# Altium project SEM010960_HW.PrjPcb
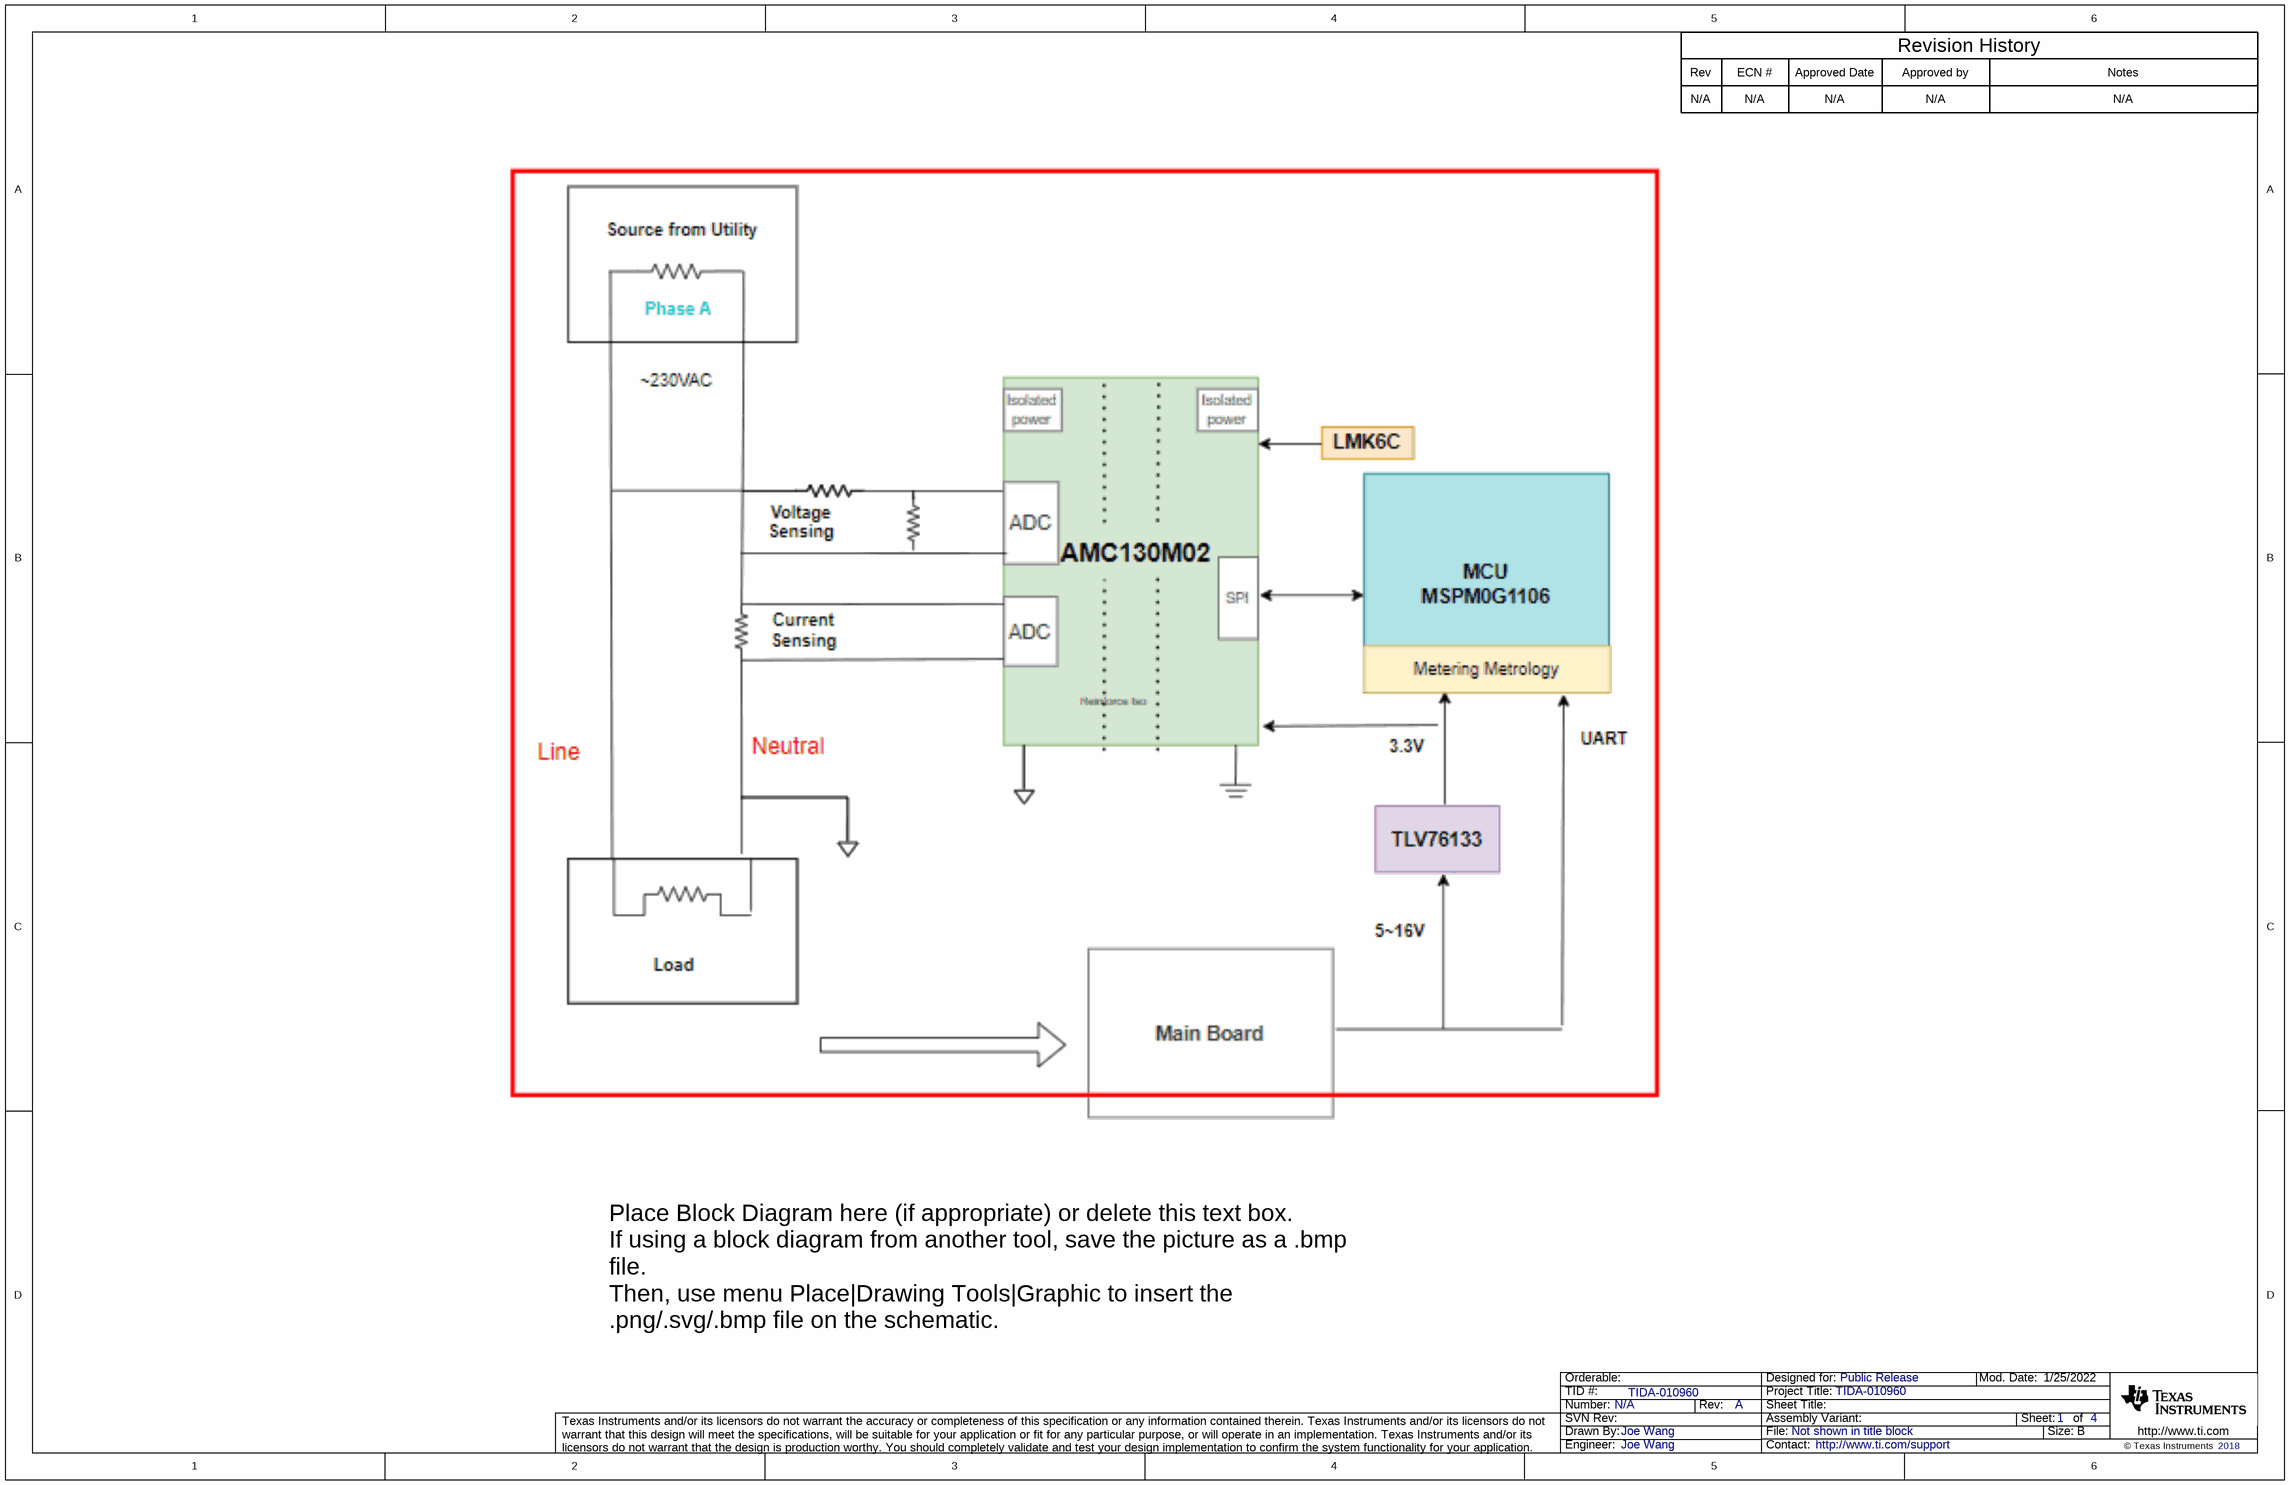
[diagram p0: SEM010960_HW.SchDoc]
CopyrightYear: 2018; PCB_Layout: Joe Wang; PCB_Rev: A; PRJ_Customer: Public Release; PRJ_Engineer: Joe Wang; PRJ_Number: N/A; PRJ_Title: TIDA-010960; SCH_Rev: A; TechSupport: http://www.ti.com/support; TID: TIDA-010960
4 sheets, 98 parts. Net scope: flat (ports and power ports of the same name join across sheets).
Board file: SEM010960_HW.PcbDoc
Sheets:
  SEM010960_HW.SchDoc
  SEM010960_HW_MSPM0.SchDoc
  SEM010960_HW_AMC.SchDoc
  SEM010960_HW_Hardware.SchDoc

## Sheet SEM010960_HW.SchDoc
size 431 x 279 mm; Date: Not shown in title block; ApprovedBy: Not shown in title block; CheckedBy: Not shown in title block; Author: Not shown in title block; CompanyName: Not shown in title block; DrawnBy: Joe Wang; Engineer: Not shown in title block; Organization: Not shown in title block; Address1: Not shown in title block; Address2: Not shown in title block; Address3: Not shown in title block; Address4: Not shown in title block; DocumentNumber: 1; Revision: Use project parameter SCH_Rev; SheetNumber: 1; SheetTotal: 4; PageSetup: Record=PageOptions¦CenterHorizontal=True¦CenterVertical=True¦PrintScale=1.00¦XCorrection=1.00¦YCorrection=1.00¦PrintKind=0¦BorderSize=5000000¦LeftOffset=0¦BottomOffset=0¦Orientation=2¦PaperLength=1000¦PaperWidth=1000¦Scale=100¦PaperSource=15¦PrintQuality=600¦MediaType=1¦DitherType=10¦PaperKind=Letter¦PrintScaleMode=1

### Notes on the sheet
- Rev
- N/A
- ECN #
- Approved Date
- Approved by
- Revision History
- Notes
- Place Block Diagram here (if appropriate) or delete this text box.
  If using a block diagram from another tool, save the picture as a .bmp file.
  Then, use menu Place|Drawing Tools|Graphic to insert the .png/.svg/.bmp file on the schematic.

## Sheet SEM010960_HW_MSPM0.SchDoc
size 431 x 279 mm; Date: Not shown in title block; ApprovedBy: Not shown in title block; CheckedBy: Not shown in title block; Author: Not shown in title block; CompanyName: Not shown in title block; DrawnBy: Joe Wang; Engineer: Not shown in title block; Organization: Not shown in title block; Address1: Not shown in title block; Address2: Not shown in title block; Address3: Not shown in title block; Address4: Not shown in title block; DocumentNumber: 2; Revision: Use project parameter SCH_Rev; SheetNumber: 2; SheetTotal: 4; PageSetup: Record=PageOptions¦CenterHorizontal=True¦CenterVertical=True¦PrintScale=1.00¦XCorrection=1.00¦YCorrection=1.00¦PrintKind=0¦BorderSize=5000000¦LeftOffset=0¦BottomOffset=0¦Orientation=2¦PaperLength=1000¦PaperWidth=1000¦Scale=100¦PaperSource=15¦PrintQuality=600¦MediaType=1¦DitherType=10¦PaperKind=Letter¦PrintScaleMode=1
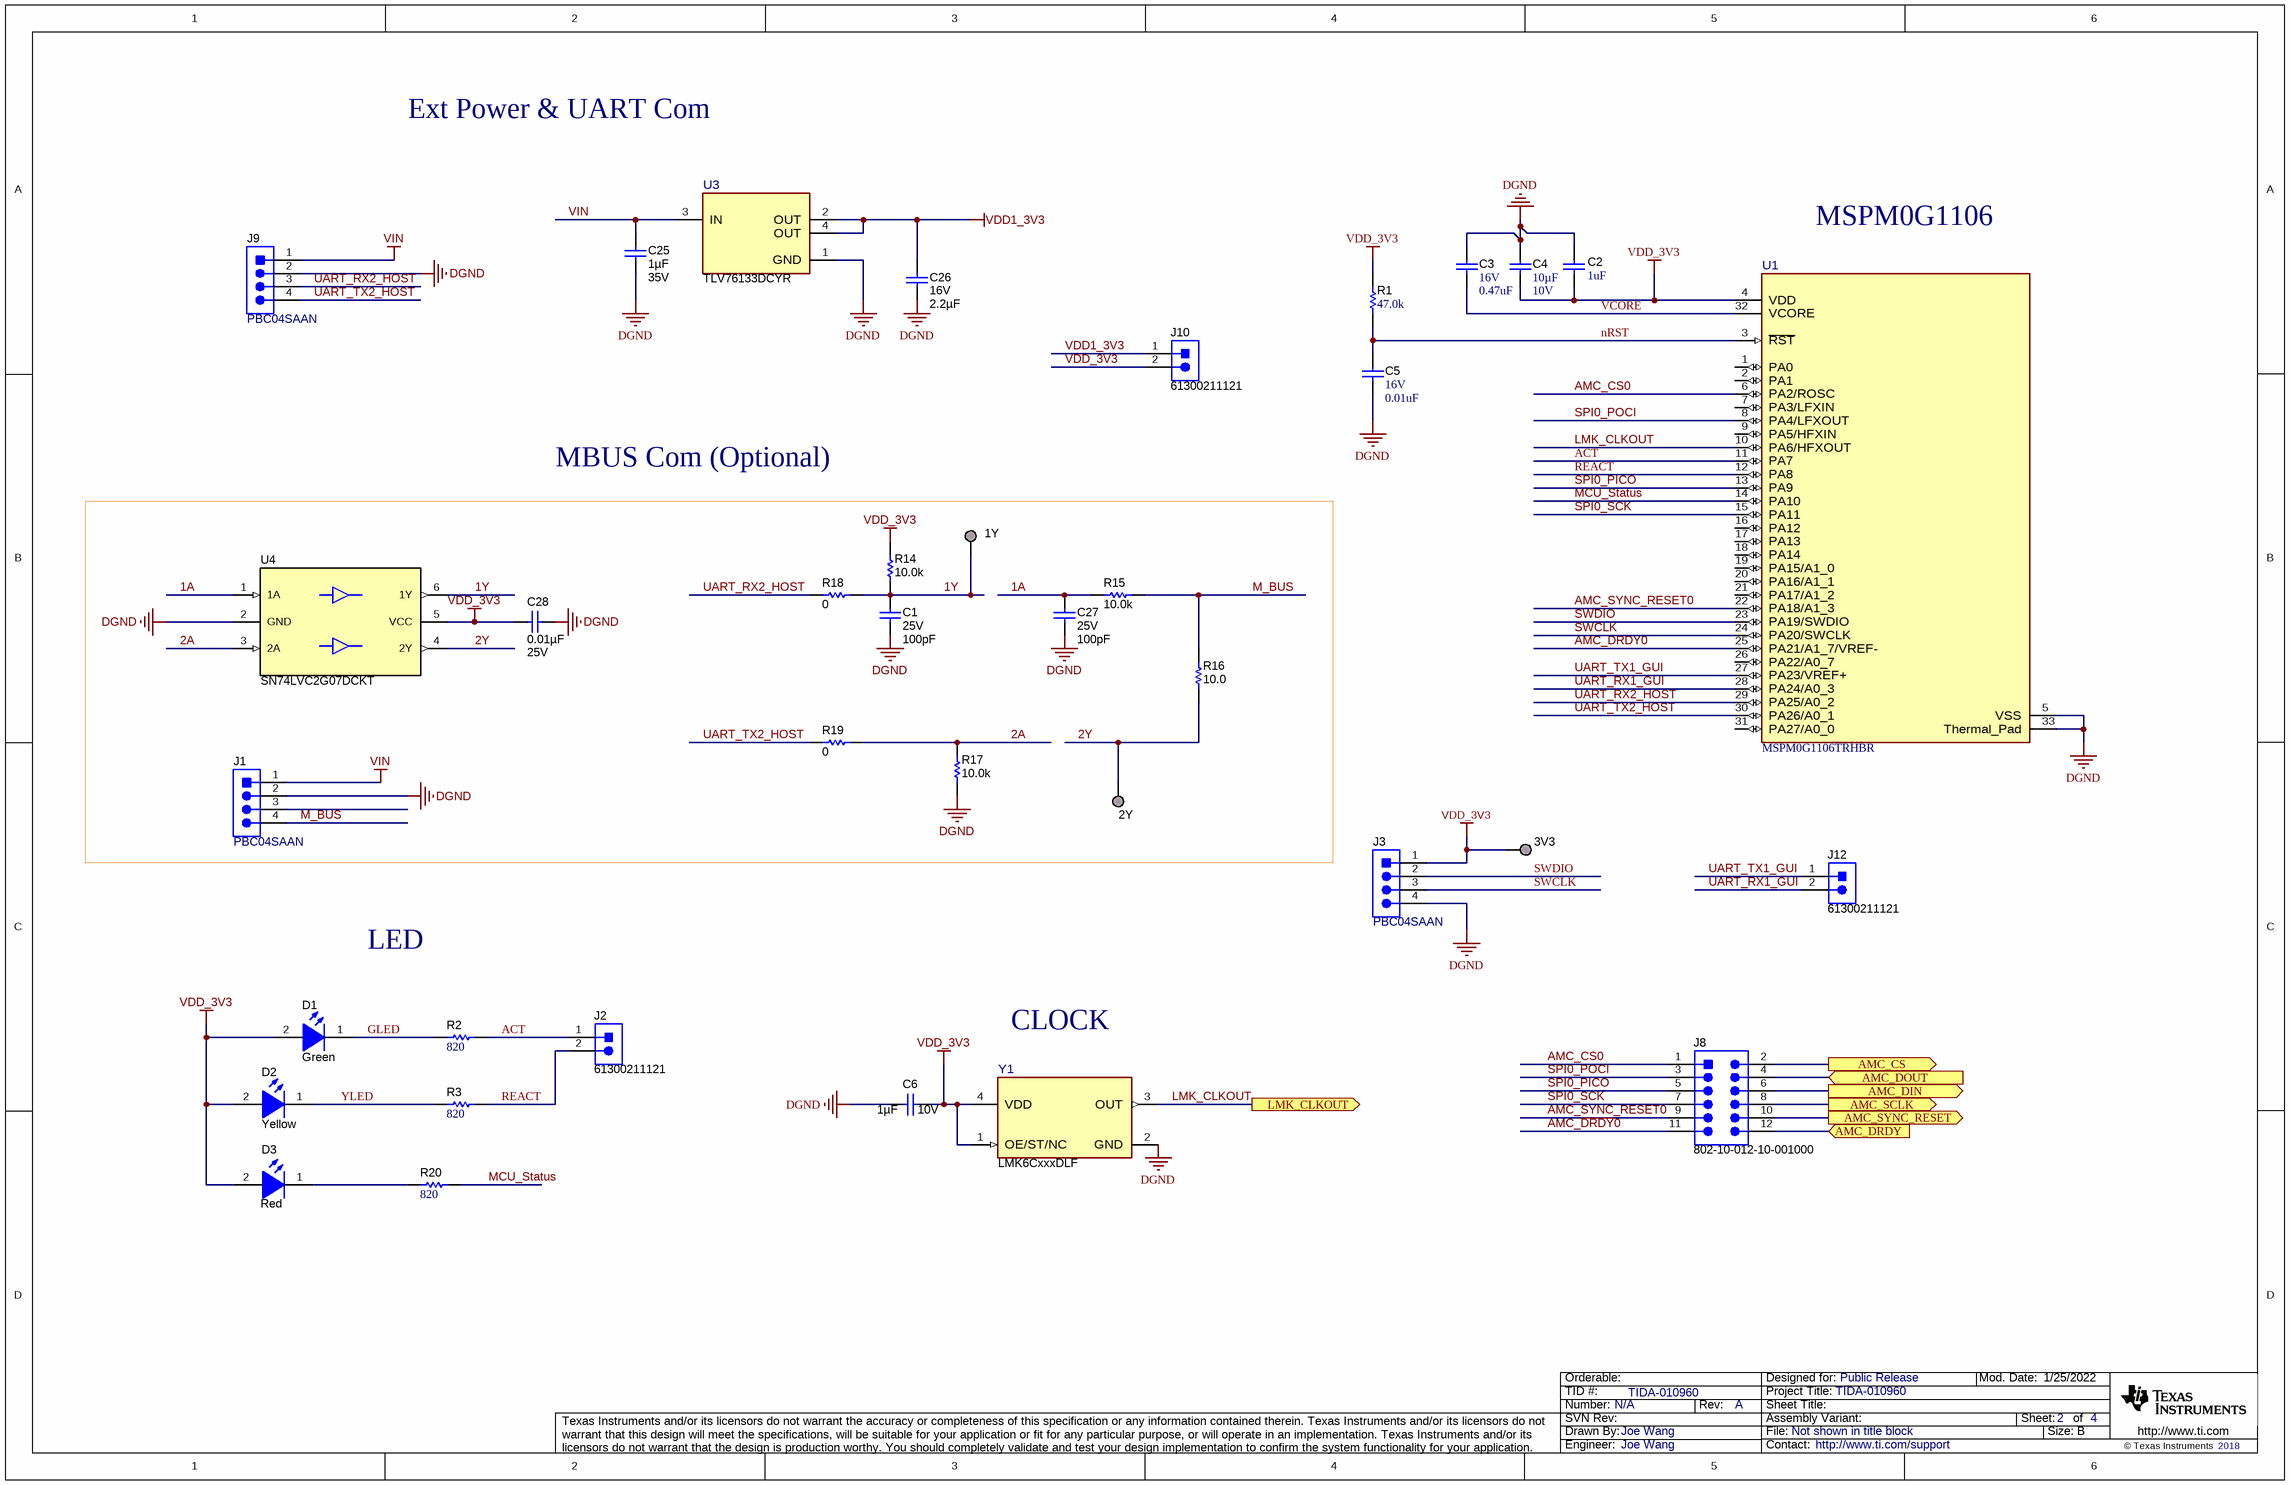
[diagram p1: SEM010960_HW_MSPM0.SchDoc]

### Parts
1Y  Testpoint_Gray  [Harwin_S2761-46R]  (value not drawn)
2Y  Testpoint_Gray  [Harwin_S2761-46R]  (value not drawn)
3V3  Testpoint_Gray  [Harwin_S2761-46R]  (value not drawn)
C1  VDC_V: 25V  ValueDisplayed: 100pF  [0402]  (hidden comment: C0402C101J3GACTU)
C2  ValueDisplayed: 1uF  [0402]  (hidden comment: GRM155R61A105KE15D)
C3  VDC_V: 16V  ValueDisplayed: 0.47uF  [0402]  (hidden comment: GRM155R61C474KE01)
C4  ValueDisplayed: 10µF  VDC_V: 10V  [0603]  (hidden comment: GRM188R61A106KAALD)
C5  VDC_V: 16V  ValueDisplayed: 0.01uF  [0402]  (hidden comment: C1005X7R1C103K050BA)
C6  Cap_F: 1µF  VDC_V: 10V  [0603]  (hidden comment: LMK107B7105KA-T)
C25  Cap_F: 1µF  VDC_V: 35V  [0603]  (hidden comment: CGA3E1X7R1V105K080AE)
C26  VDC_V: 16V  Cap_F: 2.2µF  [0603]  (hidden comment: GRM188Z71C225KE43)
C27  VDC_V: 25V  ValueDisplayed: 100pF  [0402]  (hidden comment: C0402C101J3GACTU)
C28  ValueDisplayed: 0.01µF  VDC_V: 25V  [0402]  (hidden comment: 04023C103JAT2A)
D1  value Green  [WL-SMCW_GREEN]  (hidden comment: 150060VS75000)
D2  value Yellow  [WL-SMCW_YELLOW]  (hidden comment: 150060YS75000)
D3  value Red  [WL-SMCW_RED]  (hidden comment: 150060RS75000)
J1  PBC04SAAN  [Sullins_xxC04SAAN]
J2  61300211121  [WURTH_61300211121]
J3  PBC04SAAN  [Sullins_xxC04SAAN]
J8  802-10-012-10-001000  [Mill-Max_802-10-012-10-001000]
J9  PBC04SAAN  [Sullins_xxC04SAAN]
J10  61300211121  [WURTH_61300211121]
J12  61300211121  [WURTH_61300211121]
R1  ValueDisplayed: 47.0k  [0402]  (hidden comment: RC0402FR-0747KL)
R2  value 820  [0402]  (hidden comment: RC0402FR-07820RL)
R3  value 820  [0402]  (hidden comment: RC0402FR-07820RL)
R14  ValueDisplayed: 10.0k  [0402]  (hidden comment: CRCW040210K0DHEDP)
R15  ValueDisplayed: 10.0k  [0402]  (hidden comment: CRCW040210K0DHEDP)
R16  ValueDisplayed: 10.0  [0402]  (hidden comment: CRCW040210R0FKED)
R17  ValueDisplayed: 10.0k  [0402]  (hidden comment: CRCW040210K0DHEDP)
R18  ValueDisplayed: 0  [0402]  (hidden comment: RC0402JR-070RL)
R19  ValueDisplayed: 0  [0402]  (hidden comment: RC0402JR-070RL)
R20  value 820  [0402]  (hidden comment: RC0402FR-07820RL)
U1  MSPM0G1106TRHBR  [RHB0032N-MFG]
U3  TLV76133DCYR  [DCY0004A-MFG]
U4  SN74LVC2G07DCKT  [DCK0006A_N]
Y1  LMK6CxxxDLF  [DLF0004A-MFG]

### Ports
AMC_CS (out), AMC_DIN (out), AMC_DOUT (in), AMC_DRDY (in), AMC_SCLK (out), AMC_SYNC_RESET (out), LMK_CLKOUT (out)

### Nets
DGND: C1.2 C2.2 C3.1 C4.1 C5.2 C6.2 C25.2 C26.2 C27.2 C28.2 J1.2 J3.4 J9.2 R17.1 U1.5(VSS) U1.33(Thermal_Pad) U3.1(GND) U4.2(GND) Y1.2(GND)
VDD1_3V3: C26.1 J10.1 U3.2(OUT) U3.4(OUT)
VDD_3V3: 3V3.1 C2.1 C4.2 C6.1 C28.1 D1.2(A) D2.2(A) D3.2(A) J3.1 J10.2 R1.2 R14.2 U1.4(VDD) U4.5(VCC) Y1.1(OE/ST/NC) Y1.4(VDD)
VIN: C25.1 J1.1 J9.1 U3.3(IN)
1A: C27.1 R15.1 U4.1(1A)
1Y: 1Y.1 C1.1 R14.1 R18.2 U4.6(1Y)
2A: R17.2 R19.2 U4.3(2A)
2Y: 2Y.1 R16.1 U4.4(2Y)
ACT: J2.1 R2.1 U1.11(PA7)
ADC_~{CS}: J8.2 ; port AMC_CS
ADC_DIN: J8.6 ; port AMC_DIN
ADC_DOUT: J8.4 ; port AMC_DOUT
ADC_SCLK: J8.8 ; port AMC_SCLK
AMC_CS0: J8.1 U1.6(PA2/ROSC)
AMC_~{DRDY}: J8.12 ; port AMC_DRDY
AMC_~{DRDY}0: J8.11 U1.25(PA21/A1_7/VREF-)
AMC_SYNC_RESET: J8.10 ; port AMC_SYNC_RESET
AMC_SYNC_RESET0: J8.9 U1.22(PA18/A1_3)
GLED: D1.1(K) R2.2
LMK_CLKOUT: U1.10(PA6/HFXOUT) Y1.3(OUT) ; port LMK_CLKOUT
M_BUS: J1.4 R15.2 R16.2
MCU_Status: R20.1 U1.14(PA10)
nRST: C5.1 R1.1 U1.3(~{RST})
REACT: J2.2 R3.1 U1.12(PA8)
SPI0_PICO: J8.5 U1.13(PA9)
SPI0_POCI: J8.3 U1.8(PA4/LFXOUT)
SPI0_SCK: J8.7 U1.15(PA11)
SWCLK: J3.3 U1.24(PA20/SWCLK)
SWDIO: J3.2 U1.23(PA19/SWDIO)
UART_RX1_GUI: J12.2 U1.28(PA24/A0_3)
UART_RX2_HOST: J9.3 R18.1 U1.29(PA25/A0_2)
UART_TX1_GUI: J12.1 U1.27(PA23/VREF+)
UART_TX2_HOST: J9.4 R19.1 U1.30(PA26/A0_1)
VCORE: C3.2 U1.32(VCORE)
YLED: D2.1(K) R3.2
NetD3_1: D3.1(K) R20.2

Not connected (* = marked no-connect by the designer): J1 3; U1 1(PA0) 2(PA1) 7(PA3/LFXIN) 9(PA5/HFXIN) 16(PA12) 17(PA13) 18(PA14) 19(PA15/A1_0) 20(PA16/A1_1) 21(PA17/A1_2) 26(PA22/A0_7) 31(PA27/A0_0)

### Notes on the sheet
- Ext Power & UART Com
- MSPM0G1106
- MBUS Com (Optional)
- LED
- CLOCK

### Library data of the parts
1Y 2Y 3V3 = CMP-0067619-1: Natural PC Test Point Brass, SMT; Manufacturer: Harwin; PartNumber: S2761-46R
C1 C27 = CMP-0006233-2: CAP, CERM, 100 pF, 25 V, +/- 5%, C0G/NP0, 0402; Manufacturer: Kemet; TaMin_C: -55°C; Polarized: N; SizeAreaWB_mm2: 3; Value1: Unknown; U/M: EA; Value: 100pF; TaMax_C: 125°C; SizeZ_mm: 0.6; SizeX_mm: 1; SizeY_mm: 0.5; AEC Category: Q200
C2 = CMP-0006563-2: CAP, CERM, 1 uF, 10 V, +/- 10%, X5R, 0402; Manufacturer: MuRata; TaMin_C: -55°C; Polarized: N; SizeAreaWB_mm2: 3; Value1: Unknown; U/M: EA; Value: 1uF; TaMax_C: 85°C; SizeZ_mm: 0.6; SizeX_mm: 1; SizeY_mm: 0.5; Value2: 10V; Cap_F: 1µF; AEC Category: Q200
C3 = CMP-0006600-2: CAP, CERM, 0.47 uF, 16 V, +/- 10%, X5R, 0402; Manufacturer: MuRata; TaMin_C: -55°C; Polarized: N; SizeAreaWB_mm2: 3; Value1: Unknown; U/M: EA; Value: 0.47uF; TaMax_C: 85°C; SizeZ_mm: 0.6; SizeX_mm: 1; SizeY_mm: 0.5; Cap_F: 470nF; AEC Category: Q200
C4 = CMP-0086193-1: CAP, CERM, 10 µF, 10 V,+/- 10%, X5R, 0603; Manufacturer: MuRata; SizeArea_mm2: 1.28; SizeY_mm: 0.8; TaMax_C: 85°C; TaMin_C: -55°C; Polarized: N; SizeAreaWB_mm2: 4.68; SizeZ_mm: 1; SizeX_mm: 1.6; AEC Category: Q200; U/M: EA; Value: 10uF
C5 = CMP-0006292-2: CAP, CERM, 0.01 uF, 16 V, +/- 10%, X7R, 0402; Manufacturer: TDK; TaMin_C: -55°C; Polarized: N; SizeAreaWB_mm2: 3; Value1: 0.0623 ohm; U/M: EA; Value: 0.01uF; TaMax_C: 125°C; SizeZ_mm: 0.6; SizeX_mm: 1; SizeY_mm: 0.5; Cap_F: 10nF; AEC Category: Q200; ESR_ohm: 62.3m
C6 = CMP-0080632-1: CAP, CERM, 1 µF, 10 V,+/- 10%, X7R, 0603; Manufacturer: Taiyo Yuden; SizeAreaWB_mm2: 4.68; SizeArea_mm2: 1.28; AEC Qualified: N; AEC Category: Q200; Value: 1uF; TaMax_C: 125°C; SizeZ_mm: 1; Green_REACh: Incomplete; TaMin_C: -55°C; SizeY_mm: 0.8; Green_Lifecycle: Active; U/M: EA; SizeX_mm: 1.6
C25 = CMP-0081259-1: CAP, CERM, 1 µF, 35 V,+/- 10%, X7R, AEC-Q200 Grade 1, 0603; Manufacturer: TDK; SizeAreaWB_mm2: 4.68; SizeArea_mm2: 1.28; AEC Qualified: Y; AEC Category: Q200; Value: 1uF; TaMax_C: 125°C; SizeZ_mm: 1; Polarized: N; TaMin_C: -55°C; SizeY_mm: 0.8; U/M: EA; SizeX_mm: 1.6
C26 = CMP-0007499-1: CAP, CERM, 2.2 uF, 16 V, +/- 10%, X7R, 0603; Manufacturer: MuRata; TaMin_C: -55°C; Polarized: N; SizeAreaWB_mm2: 4.68; Value1: Unknown; U/M: EA; Value: 2.2uF; TaMax_C: 125°C; SizeZ_mm: 1; SizeX_mm: 1.6; SizeY_mm: 0.8; SizeArea_mm2: 1.28; AEC Category: Q200
C28 = CMP-0085568-1: CAP, CERM, 0.01 µF, 25 V,+/- 5%, X7R, 0402; Manufacturer: AVX; AEC Category: Q200; SizeAreaWB_mm2: 3; SizeArea_mm2: 0.5; Polarized: N; TaMin_C: -55°C; Value: 0.01uF; U/M: EA; SizeX_mm: 1; Cap_F: 10nF; SizeZ_mm: 0.6; TaMax_C: 125°C
D1 = CMP-0002894-2: LED, Green, SMD; Manufacturer: Wurth Elektronik; Type: AlInGaP; Vf_V: 2V; Io_A: 20mA; Value1: W
D2 = CMP-0002892-3: LED, Yellow, SMD; Manufacturer: Wurth Elektronik; Type: AlInGaP; Vf_V: 2V; Io_A: 20mA; Value1: W
D3 = CMP-0002947-2: LED, Red, SMD; Manufacturer: Wurth Elektronik; Io_A: 30mA; Power_TotalModule: 72mW; Vr_V: 5V; Tjmax_C: 85°C; Value1: 0.072W; U/M: EA; Angle: 140; Vf_V: 2V; Type: AlInGaP
J1 J3 J9 = CMP-0054583-1: Header, 2.54 mm, 4x1, Gold, TH; Manufacturer: Sullins Connector Solutions; CNHeader: TRUE; Current_A: 3A; Green_Lifecycle: Not Set; Shrouded: N; Gender: Male; Green_REACh: Incomplete; Voltage_V: 1.8kV; Row_Count: 1; Pitch_mm: 2.54; CT: FALSE; Cert_UL: Y
J2 J10 J12 = CMP-0054794-2: Header, 2.54 mm, 2x1, Gold, TH; Manufacturer: Wurth Elektronik; Green_Lifecycle: Active; Shrouded: N; Gender: Male; Green_REACh: Passed; Row_Count: 1; Pitch_mm: 2.54; Cert_UL: Y
J8 = CMP-0055098-2: Header, 2.54 mm, 6x2, Gold, TH; Manufacturer: Mill-Max; Shrouded: N; Gender: Male; Row_Count: 2; RowSpacing_mm: 2.54
R1 = CMP-0026737-1: RES, 47.0 k, 1%, 0.0625 W, 0402; Manufacturer: Yageo America; Power_W: 62.5mW; TempCo: 100 ppm/C; Value_Code: 47k0; Value: 47.0k; Res_ohm: 47k; SizeX_mm: 1; SizeY_mm: 0.5; SizeZ_mm: 0.6; AEC Qualified: N; VDC_V: 50V; AEC Category: Q200; U/M: EA
R2 R3 R20 = CMP-0026743-1: RES, 820, 1%, 0.063 W, 0402; Manufacturer: Yageo America; Value_Code: 820R; Power_W: 63mW; Value2: 0.063W; VDC_V: 50V; TempCo: 100 ppm/C; U/M: EA; AEC Category: Q200; AEC Qualified: N; SizeArea_mm2: 0.5; SizeX_mm: 1; SizeZ_mm: 0.6
R14 R15 R17 = CMP-0026769-1: RES, 10.0 k, 0.5%, 0.063 W, 0402; Manufacturer: Vishay-Dale; Power_W: 63mW; TempCo: 50 ppm/C; Value_Code: 10k0; U/M: EA; Value: 10.0k; EIA_Code: E192; Res_ohm: 10k; SizeX_mm: 1; SizeY_mm: 0.5; SizeZ_mm: 0.6; Value2: 0.063W; VDC_V: 50V; AEC Category: Q200
R16 = CMP-0025963-3: RES, 10.0, 1%, 0.063 W, AEC-Q200 Grade 0, 0402; Manufacturer: Vishay-Dale; Power_W: 63mW; TempCo: 100 ppm/C; Value_Code: 10R0; Value: 10.0; EIA_Code: E96; Res_ohm: 10; SizeX_mm: 1; SizeY_mm: 0.5; SizeZ_mm: 0.6; Value2: 0.063W; AEC Qualified: Y; VDC_V: 50V; AEC Category: Q200; AEC Grade: 0
R18 R19 = CMP-0027004-1: RES, 0, 5%, 0.063 W, 0402; Manufacturer: Yageo America; Power_W: 63mW; TempCo: 200 ppm/C; Value_Code: 0000; U/M: EA; Value: 0; EIA_Code: E24; SizeX_mm: 1; SizeY_mm: 0.5; SizeZ_mm: 0.6; Value2: 0.063W; VDC_V: 50V; AEC Category: Q200
U1 = CMP-0095751-1: Mixed-Signal Microcontrollers VQFN32 ARM 32-bit Cortex-M0+ 80MHz 28 I/O's 64KB Flash 32KB SRAM; Manufacturer: Texas Instruments; AEC Qualified: No; Interface: I2C,SPI,UART,LIN,IrDA,SMBus; TJmax_C: +130°C; Number Of A/D Converters: 2; SizeZ_mm: 0.9mm; Max Supply Voltage: 3.6V; Core Architecture: ARM Cortex-M0+; Number Of Cores: 1; Standoff Height: 0mm; Memory Size: 64KBytes; Data Bus Width: 32bits; Number Of I/Os: 28; Number Of Timers/Counters: 7; Number Of Pwm Channels: 8; Number Of Uart Channels: 4; Ram Size: 32KBytes; Number Of Adc Channels: 10; TaMin_C: -40°C; Min Supply Voltage: 1.62V; TaMax_C: +105°C
U3 = CMP-0122558-1: 1-A 16-V high-PSRR linear voltage regulator 4-SOT-223 -40 to 125; Manufacturer: Texas Instruments; SizeZ_mm: 1.8mm; AEC Qualified: No; Accuracy Percentage: 1%; Dropout Voltage: 0.9V; Max Supply Voltage: 16V; Min Supply Voltage: 4.8V; Nominal Supply Current: 65uA; Number Of Outputs: 1; Output Type: Fixed; Output Voltage: 3.3V; Standoff Height: 0.02mm; TJmax_C: +125°C
U4 = CMP-0051787-3: Dual Buffer/Driver with Open-Drain Output, DCK0006A (SOT-SC70-6); Manufacturer: Texas Instruments; Alternate PartNumber: SN74LVC2G07DCKR; Output Type: CMOS; Bits(#): 2; Input Type: CMOS/TTL; Technology Family: LVC; Schmitt Trigger: No; VCC(Max)(V): 5.5; Sub-Family: Inverting Buffer/Driver; Rating: Catalog; Output Drive (IOL/IOH)(Max)(mA): 32/-32; ICC @ Nom Voltage(Max)(mA): 0.01; VCC(Min)(V): 1.65; F @ Nom Voltage(Max)(Mhz): 150; Logic: True; Voltage(Nom)(V): 1.8,2.5,3.3,5; tpd @ Nom Voltage(Max)(ns): 8.6,4.4,3.7,2.9; AEC Category: Q200; AEC Qualified: N; CompType: IC; Green_Lifecycle: Active; Green_REACh: Passed; SizeAreaWB_mm2: 9.3; SizeArea_mm2: 4.2; SizeX_mm: 2.1; SizeY_mm: 2.0; SizeZ_mm: 1.1
Y1 = CMP-0122603-1: Low Jitter, High-Performance BAW Oscillator; Manufacturer: Texas Instruments; SizeZ_mm: 1mm; AEC Qualified: No; Frequency Stability: 25ppm; Standoff Height: 0mm; TaMax_C: +105°C; TaMin_C: -40°C; TJmax_C: +125°C

## Sheet SEM010960_HW_AMC.SchDoc
size A3; Date: Not shown in title block; ApprovedBy: Not shown in title block; CheckedBy: Not shown in title block; Author: Not shown in title block; CompanyName: Not shown in title block; Engineer: Not shown in title block; Organization: Not shown in title block; Address1: Not shown in title block; Address2: Not shown in title block; Address3: Not shown in title block; Address4: Not shown in title block; DocumentNumber: 1; Revision: Use project parameter SCH_Rev; SheetNumber: 3; SheetTotal: 4; PageSetup: Record=PageOptions¦CenterHorizontal=True¦CenterVertical=True¦PrintScale=0.69¦XCorrection=1.00¦YCorrection=1.00¦PrintKind=0¦BorderSize=5000000¦LeftOffset=0¦BottomOffset=0¦Orientation=2¦PaperLength=1000¦PaperWidth=1000¦Scale=100¦PaperSource=15¦PrintQuality=600¦MediaType=1¦DitherType=10¦PaperKind=Letter¦PrintScaleMode=1
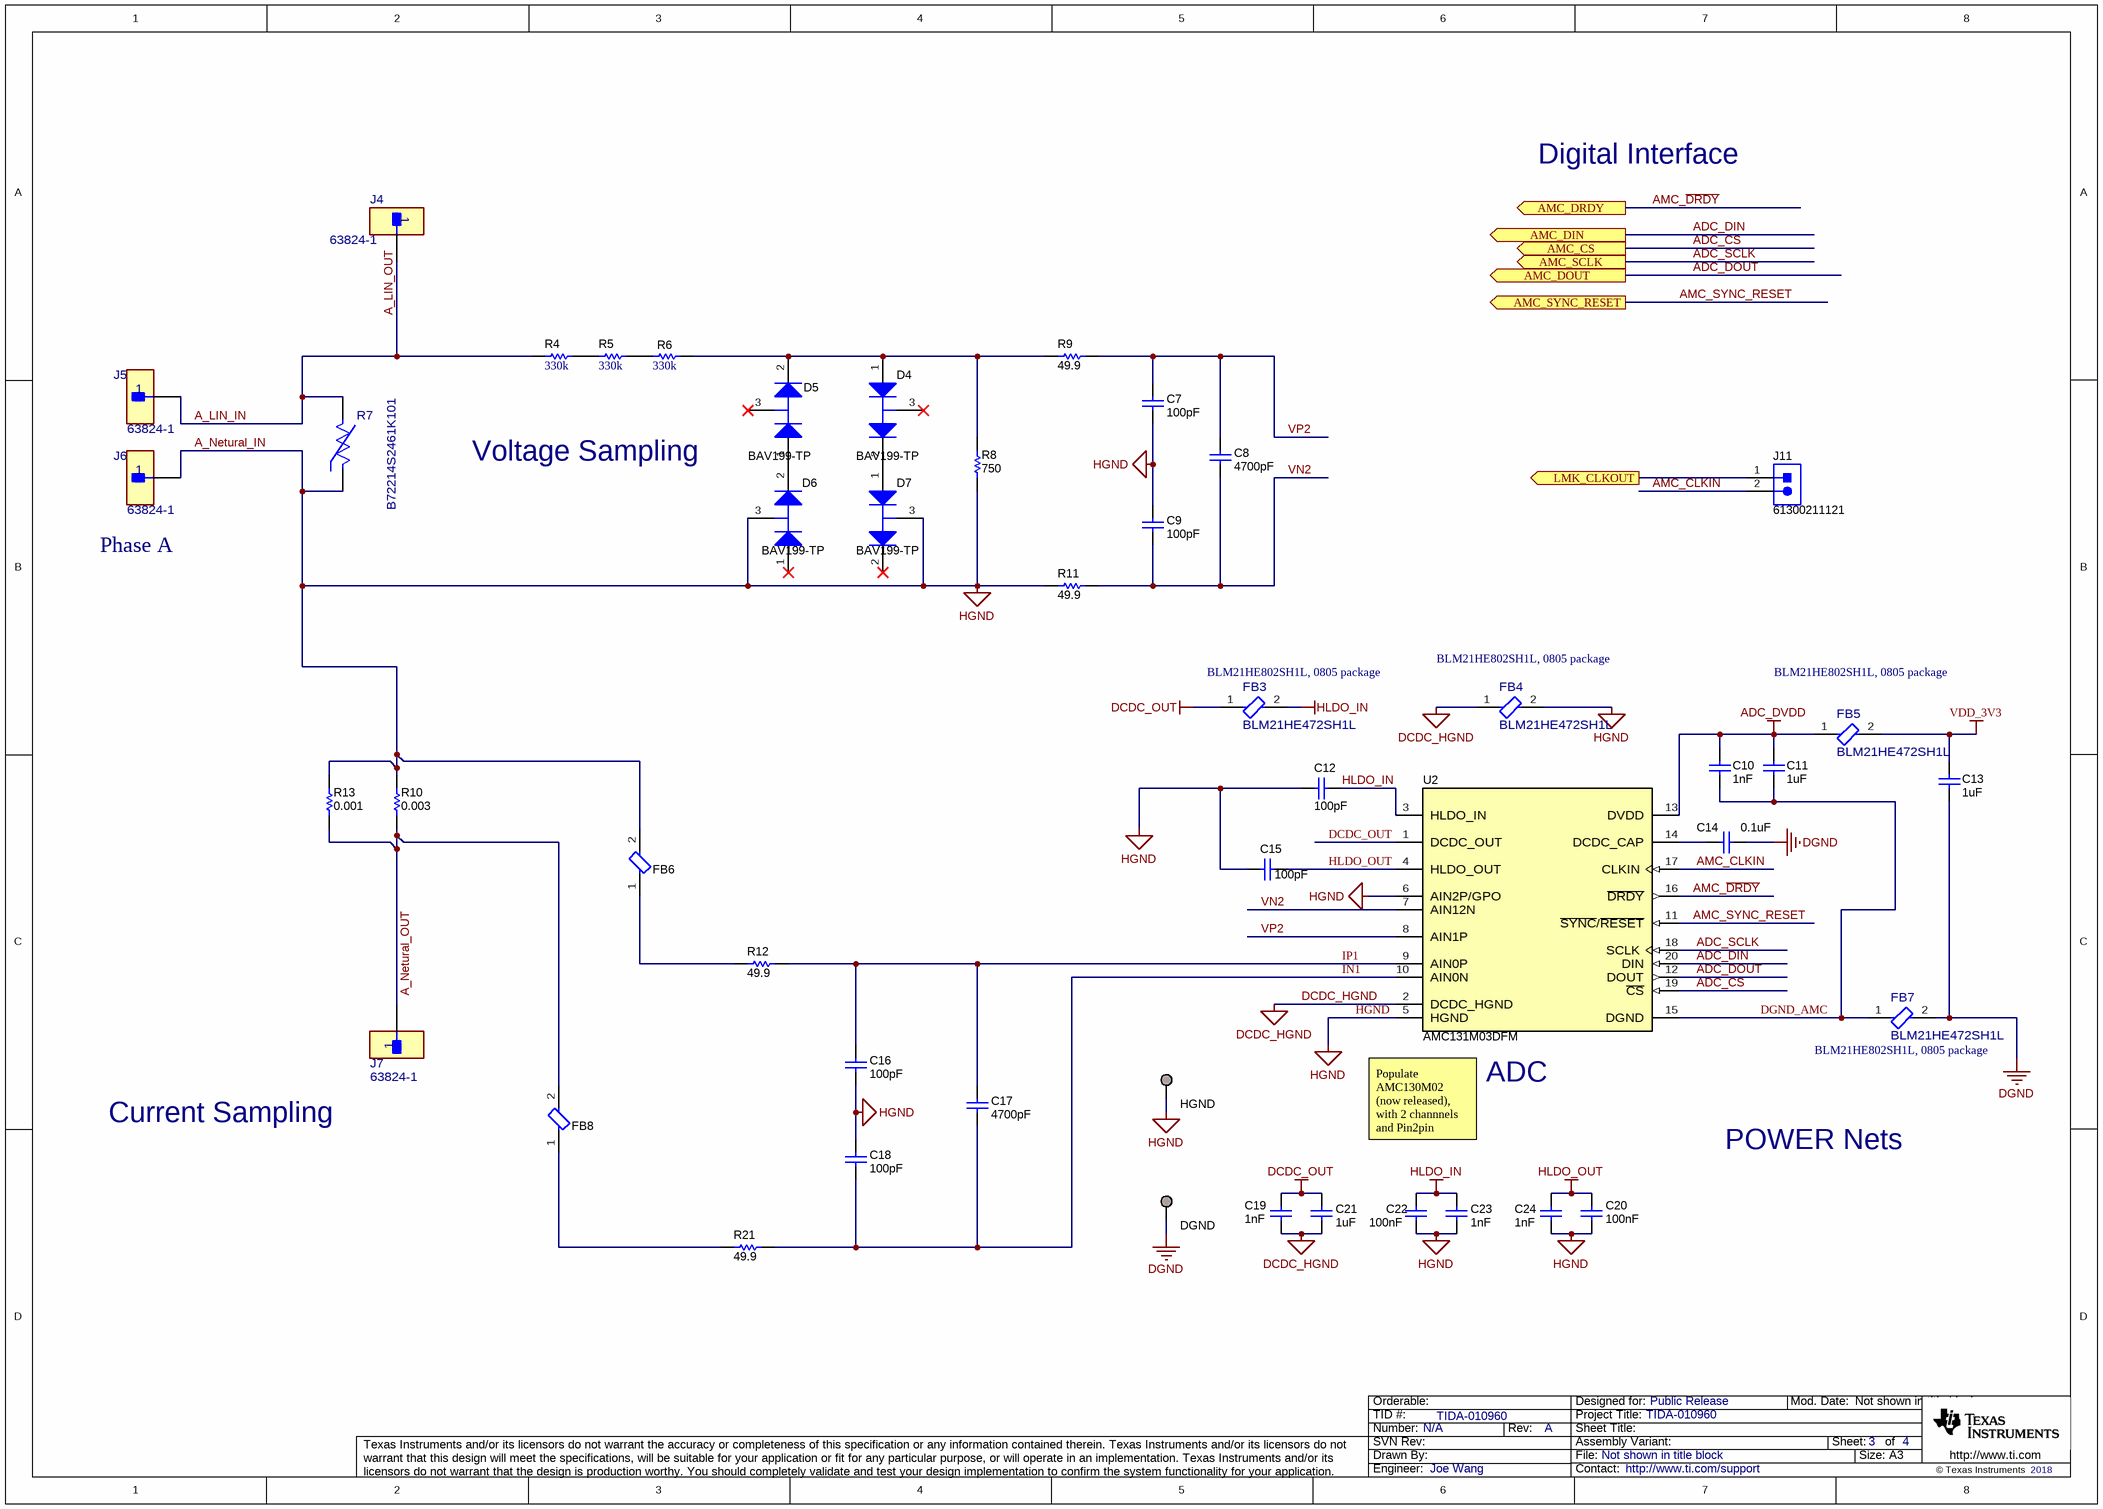
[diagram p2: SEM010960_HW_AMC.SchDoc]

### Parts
C7  ValueDisplayed: 100pF  [0603_HV]  (hidden comment: 885012006057)
C8  ValueDisplayed: 4700pF  [0603_HV]  (hidden comment: C0603C472J1GAC7867)
C9  ValueDisplayed: 100pF  [0603_HV]  (hidden comment: 885012006057)
C10  Cap_F: 1nF  [0603]  (hidden comment: C0603C102K5RACTU)
C11  ValueDisplayed: 1uF  [0603]  (hidden comment: C0603C105K3RACTU)
C12  ValueDisplayed: 100pF  [0603]  (hidden comment: 885012006057)
C13  ValueDisplayed: 1uF  [0603]  (hidden comment: C0603C105K3RACTU)
C14  value 0.1uF  [0603]  (hidden comment: C1608X7R1H104K080AA)
C15  ValueDisplayed: 100pF  [0603]  (hidden comment: 885012006057)
C16  ValueDisplayed: 100pF  [0603_HV]  (hidden comment: 885012006057)
C17  ValueDisplayed: 4700pF  [0603_HV]  (hidden comment: C0603C472J1GAC7867)
C18  ValueDisplayed: 100pF  [0603_HV]  (hidden comment: 885012006057)
C19  Cap_F: 1nF  [0603]  (hidden comment: C0603C102K5RACTU)
C20  Cap_F: 100nF  [0603]  (hidden comment: C1608X7R1H104K080AA)
C21  ValueDisplayed: 1uF  [0603]  (hidden comment: C0603C105K3RACTU)
C22  Cap_F: 100nF  [0603]  (hidden comment: C1608X7R1H104K080AA)
C23  Cap_F: 1nF  [0603]  (hidden comment: C0603C102K5RACTU)
C24  Cap_F: 1nF  [0603]  (hidden comment: C0603C102K5RACTU)
D4  BAV199-TP  [SOT-23L]
D5  BAV199-TP  [SOT-23L]
D6  BAV199-TP  [SOT-23L]
D7  BAV199-TP  [SOT-23L]
DGND  Testpoint_Gray  [Harwin_S2761-46R]  (value not drawn)
FB3  BLM21HE472SH1L  [FP-BLM21HE472SH1L_0805-MFG]
FB4  BLM21HE472SH1L  [FP-BLM21HE472SH1L_0805-MFG]
FB5  BLM21HE472SH1L  [FP-BLM21HE472SH1L_0805-MFG]
FB6  74269244182  [FP-74269244182_0402-MFG]  (value not drawn)
FB7  BLM21HE472SH1L  [FP-BLM21HE472SH1L_0805-MFG]
FB8  74269244182  [FP-74269244182_0402-MFG]  (value not drawn)
HGND  Testpoint_Gray  [Harwin_S2761-46R]  (value not drawn)
J4  63824-1  [FP-63824-1_CONN_7MM92_3MM11-MFG]
J5  63824-1  [FP-63824-1_CONN_7MM92_3MM11-MFG]
J6  63824-1  [FP-63824-1_CONN_7MM92_3MM11-MFG]
J7  63824-1  [FP-63824-1_CONN_7MM92_3MM11-MFG]
J11  61300211121  [WURTH_61300211121]
R4  ValueDisplayed: 330k  [TNPV1206]  (hidden comment: TNPV1206330KBEEN)
R5  ValueDisplayed: 330k  [TNPV1206]  (hidden comment: TNPV1206330KBEEN)
R6  ValueDisplayed: 330k  [TNPV1206]  (hidden comment: TNPV1206330KBEEN)
R7  B72214S2461K101  [FP-B72214S2461K101_RADIAL-MFG]
R8  ValueDisplayed: 750  [0603]  (hidden comment: RG1608P-751-B-T5)
R9  ValueDisplayed: 49.9  [0603]  (hidden comment: CRCW060349R9FKEA)
R10  ValueDisplayed: 0.003  [CRE2512-R1_R4]  (hidden comment: CRE2512-FZ-R003E-3)
R11  ValueDisplayed: 49.9  [0603]  (hidden comment: CRCW060349R9FKEA)
R12  ValueDisplayed: 49.9  [0603]  (hidden comment: CRCW060349R9FKEA)
R13  ValueDisplayed: 0.001  [1206]  (hidden comment: CRF1206-FZ-R001ELF)
R21  ValueDisplayed: 49.9  [0603]  (hidden comment: CRCW060349R9FKEA)
U2  AMC131M03DFM  [DFM0020A-MFG]

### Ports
AMC_CS (out), AMC_DIN (out), AMC_DOUT (out), AMC_DRDY (out), AMC_SCLK (out), AMC_SYNC_RESET (out), LMK_CLKOUT (out)

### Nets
A_Netural_IN: C7.2 C9.1 C12.1 C15.1 C16.2 C18.1 C20.2 C22.2 C23.2 C24.2 D6.3(C) D7.3(C) FB4.2 FB6.2 HGND.1 J6.1 R7.2 R8.1 R10.2 R11.1 R13.2 U2.5(HGND) U2.6(AIN2P/GPO)  [also labelled HGND]
ADC_DVDD: C10.1 C11.2 FB5.1 U2.13(DVDD)
DCDC_HGND: C19.2 C21.1 FB4.1 U2.2(DCDC_HGND)
DCDC_OUT: C19.1 C21.2 FB3.1 U2.1(DCDC_OUT)
DGND: C13.1 C14.2 DGND.1 FB7.2
HLDO_IN: C12.2 C22.1 C23.1 FB3.2 U2.3(HLDO_IN)
HLDO_OUT: C15.2 C20.1 C24.1 U2.4(HLDO_OUT)
VDD_3V3: C13.2 FB5.2
A_LIN_IN: J4.1 J5.1 R4.2 R7.1  [also labelled A_LIN_OUT]
A_Netural_OUT: FB8.2 J7.1 R10.1 R13.1
ADC_~{CS}: U2.19(~{CS}) ; port AMC_CS
ADC_DIN: U2.20(DIN) ; port AMC_DIN
ADC_DOUT: U2.12(DOUT) ; port AMC_DOUT
ADC_SCLK: U2.18(SCLK) ; port AMC_SCLK
AMC_CLKIN: J11.2 U2.17(CLKIN)
AMC_~{DRDY}: U2.16(~{DRDY}) ; port AMC_DRDY
AMC_SYNC_RESET: U2.11(~{SYNC}/~{RESET}) ; port AMC_SYNC_RESET
DGND_AMC: C10.2 C11.1 FB7.1 U2.15(DGND)
IN1: C17.2 C18.2 R21.2 U2.10(AIN0N)
IP1: C16.1 C17.1 R12.2 U2.9(AIN0P)
LMK_CLKOUT: J11.1 ; port LMK_CLKOUT
VN2: C8.2 C9.2 R11.2 U2.7(AIN12N)
VP2: C7.1 C8.1 R9.2 U2.8(AIN1P)
NetC14_1: C14.1 U2.14(DCDC_CAP)
NetD4_1: D4.1(A) D5.2(K) R6.2 R8.2 R9.1
NetD4_2: D4.2(K) D7.1(A)
NetD5_1: D5.1(A) D6.2(K)
NetFB6_1: FB6.1 R12.1
NetFB8_1: FB8.1 R21.1
NetR4_1: R4.1 R5.2
NetR5_1: R5.1 R6.1

Not connected (* = marked no-connect by the designer): D4 3(C)*; D5 3(C)*; D6 1(A)*; D7 2(K)*

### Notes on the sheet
- Digital Interface
- Voltage Sampling
- Phase A
- (near FB3) BLM21HE802SH1L, 0805 package
- (near FB4) BLM21HE802SH1L, 0805 package
- BLM21HE802SH1L, 0805 package
- (near FB7) BLM21HE802SH1L, 0805 package
- Current Sampling
- (near U2) ADC
- (near U2) Populate AMC130M02 (now released), with 2 channnels and Pin2pin package.
- POWER Nets

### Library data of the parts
C7 C9 C16 C18 = CMP-0006822-4: CAP, CERM, 100 pF, 50 V, +/- 5%, C0G/NP0, 0603; Manufacturer: Wurth Elektronik; TaMin_C: -55°C; Polarized: N; SizeAreaWB_mm2: 4.68; Value1: Unknown; U/M: EA; Value: 100pF; TaMax_C: 125°C; SizeZ_mm: 1; SizeX_mm: 1.6; SizeY_mm: 0.8; Cap_Case: 0603; Value2: 50V; SizeArea_mm2: 1.28; AEC Category: Q200
C8 C17 = CMP-0006941-4: CAP, CERM, 4700 pF, 100 V, +/- 5%, C0G/NP0, 0603; Manufacturer: Kemet; TaMin_C: -55°C; Polarized: N; SizeAreaWB_mm2: 4.68; Value1: Unknown; U/M: EA; Value: 4700pF; TaMax_C: 125°C; SizeZ_mm: 1; SizeX_mm: 1.6; SizeY_mm: 0.8; Cap_Case: 0603; Value2: 100V; SizeArea_mm2: 1.28; Cap_F: 4.7nF; AEC Category: Q200
C10 C19 C23 C24 = CMP-0006847-4: CAP, CERM, 1000 pF, 50 V, +/- 10%, X7R, 0603; Manufacturer: Kemet; TaMin_C: -55°C; Polarized: N; SizeAreaWB_mm2: 4.68; Value1: Unknown; U/M: EA; Value: 1000pF; TaMax_C: 125°C; SizeZ_mm: 1; SizeX_mm: 1.6; SizeY_mm: 0.8; Value2: 50V; SizeArea_mm2: 1.28; AEC Category: Q200
C11 C13 C21 = CMP-0006867-4: CAP, CERM, 1 uF, 25 V, +/- 10%, X7R, 0603; Manufacturer: Kemet; TaMin_C: -55°C; Polarized: N; SizeAreaWB_mm2: 4.68; Value1: Unknown; U/M: EA; Value: 1uF; TaMax_C: 125°C; SizeZ_mm: 1; SizeX_mm: 1.6; SizeY_mm: 0.8; Value2: 25V; SizeArea_mm2: 1.28; CompType: Capacitor; Cap_F: 1µF; AEC Category: Q200
C12 C15 = CMP-0006822-4: CAP, CERM, 100 pF, 50 V, +/- 5%, C0G/NP0, 0603; Manufacturer: Wurth Elektronik; TaMin_C: -55°C; Polarized: N; SizeAreaWB_mm2: 4.68; Value1: Unknown; U/M: EA; Value: 100pF; TaMax_C: 125°C; SizeZ_mm: 1; SizeX_mm: 1.6; SizeY_mm: 0.8; Value2: 50V; SizeArea_mm2: 1.28; AEC Category: Q200
C14 = CMP-0007044-5: CAP, CERM, 0.1 uF, 50 V, +/- 10%, X7R, 0603; Manufacturer: TDK; TaMin_C: -55°C; ESR_ohm: 29.6m; Polarized: N; SizeAreaWB_mm2: 4.68; Value1: 0.0296 ohm; U/M: EA; TaMax_C: 125°C; SizeZ_mm: 1; SizeX_mm: 1.6; SizeY_mm: 0.8; Value2: 50V; SizeArea_mm2: 1.28; IRMS_A: 971.99mA; AEC Category: Q200
C20 C22 = CMP-0007044-5: CAP, CERM, 0.1 uF, 50 V, +/- 10%, X7R, 0603; Manufacturer: TDK; TaMin_C: -55°C; ESR_ohm: 29.6m; Polarized: N; SizeAreaWB_mm2: 4.68; Value1: 0.0296 ohm; U/M: EA; Value: 0.1uF; TaMax_C: 125°C; SizeZ_mm: 1; SizeX_mm: 1.6; SizeY_mm: 0.8; Value2: 50V; SizeArea_mm2: 1.28; IRMS_A: 971.99mA; AEC Category: Q200
D4-D7 = CMP-0076968-2: Diode, Switching, 70 V, 0.215 A, SOT-23; Manufacturer: Micro Commercial Components; SizeZ_mm: 1.1; Vr_V: 70V; Value1: 0.215A; SizeArea_mm2: 7.5; TJmax_C: 150°C; SizeY_mm: 3.0; AEC Category: Q101; SizeAreaWB_mm2: 14.0; Io_A: 215mA; Value: 70V; SizeX_mm: 2.5; Green_Lifecycle: Not Set; Green_REACh: Incomplete
DGND HGND = CMP-0067619-1: as 1Y on sheet SEM010960_HW_MSPM0
FB3-FB5 FB7 = CMP-0037616-1: 4.7 kOhms @ 100 MHz 1 Signal Line Ferrite Bead 0805 (2012 Metric) 850mA 400mOhm; Manufacturer: Murata; DCR_ohm: 0.4; SizeZ_mm: 1.45mm; AEC Grade: Grade 1; AEC Qualified: Yes; Impedance At Frequency: 4700Ω @ 100MHz
FB6 FB8 = CMP-0091663-1: 1.8 kOhms @ 100MHz 1 Power, Signal Line Ferrite Bead 0402 (1005 Metric) 210mA 2.1Ohm; Manufacturer: Wurth Electronics; SizeZ_mm: 0.55mm; AEC Qualified: No; DCR_ohm: 2.1; Tolerance_%: 25%; Test Frequency: 1GHz; Impedance At Frequency: 1800Ω @ 100MHz
J4-J7 = CMP-0089624-1: Manufacturer: TE Connectivity; SizeZ_mm: 10.71mm; Conn Gender: Male; Conn Orientation: Straight; AEC Qualified: No; Import Ts: 1521847382; ContactFinish: Tin,Nickel; Current_A: 20A; Ciiva Ids: 766930
J11 = CMP-0054794-2: as J2 on sheet SEM010960_HW_MSPM0
R4-R6 = CMP-0018811-2: RES, 330 k, 0.1%, 1 W, 1206; Manufacturer: Vishay Draloric; Power_W: 1W; TempCo: 25 ppm/C; U/M: EA; Value: 330k; SizeX_mm: 3.2; SizeY_mm: 1.6; SizeZ_mm: 0.65; SizeArea_mm2: 5.12; AEC Qualified: N; VDC_V: 700V; AEC Category: Q200
R7 = CMP-0049856-1: Var MOV 460VAC/615VDC 5000A 750V Thru-Hole Radial Bulk; Manufacturer: TDK; SizeZ_mm: 19mm; AEC Qualified: No; Cap_F: 260pF; Clamping Voltage: 1240V; Vc: 50A; VDC_V: 615V; Voltage Tolerance: 10%
R8 = CMP-0023597-2: RES, 750, 0.1%, 0.1 W, 0603; Manufacturer: Susumu Co Ltd; Power_W: 100mW; TempCo: 25 ppm/C; Value_Code: 750R; U/M: EA; Value: 750; EIA_Code: E192; SizeX_mm: 1.6; SizeY_mm: 0.8; SizeZ_mm: 1; Value2: 0.1W; SizeArea_mm2: 1.28; VDC_V: 75V; AEC Category: Q200
R9 R11 R12 R21 = CMP-0022448-2: RES, 49.9, 1%, 0.1 W, 0603; Manufacturer: Vishay-Dale; Power_W: 100mW; TempCo: 100 ppm/C; Value_Code: 49R9; U/M: EA; Value: 49.9; EIA_Code: E96; SizeX_mm: 1.6; SizeY_mm: 0.8; SizeZ_mm: 1; Value2: 0.1W; SizeArea_mm2: 1.28; VDC_V: 75V; AEC Category: Q200
R10 = CMP-0015750-2: RES, 0.003, 1%, 3 W, AEC-Q200 Grade 0, 2512; Manufacturer: Bourns; Power_W: 3W; TempCo: 50 ppm/C; Value_Code: 3L000; U/M: EA; Value: 0.003; EIA_Code: E96; Res_ohm: 3m; SizeX_mm: 6.45; SizeY_mm: 3.35; SizeZ_mm: 0.9; SizeArea_mm2: 21.6075; AEC Qualified: Y; AEC Grade: 0; AEC Category: Q200
R13 = CMP-0078821-1: RES, 0.001, 1%, 1 W, AEC-Q200 Grade 0, 1206; Manufacturer: Bourns; Value_Code: 1L000; SizeArea_mm2: 5.12; AEC Qualified: Y; AEC Category: Q200; Res_ohm: 1m; Value: 0.001; SizeZ_mm: 1.35; EIA_Code: E96; TempCo: 50 ppm/C; AEC Grade: 0; SizeY_mm: 1.6; Power_W: 1W; SizeX_mm: 3.2
U2 = CMP-0093943-1: 3-Channel, Simultaneously-Sampling, 24-Bit, Reinforced Isolated DeltaSigma ADC With Integrated DC/DC Converter; Manufacturer: Texas Instruments; Interface: SPI; TaMax_C: +125°C; Standoff Height: 0.1mm; Resolution: 24bits; Max Supply Voltage: 5.5V; Data Polarity: Differential; Min Supply Voltage: 3V; TJmax_C: +150°C; Number Of Channels: 3; Sampling Rate: 32ksps; TaMin_C: -40°C; SizeZ_mm: 3.55mm; AEC Qualified: No

## Sheet SEM010960_HW_Hardware.SchDoc
size 431 x 279 mm; Date: Not shown in title block; ApprovedBy: Not shown in title block; CheckedBy: Not shown in title block; Author: Not shown in title block; CompanyName: Not shown in title block; Engineer: Not shown in title block; Organization: Not shown in title block; Address1: Not shown in title block; Address2: Not shown in title block; Address3: Not shown in title block; Address4: Not shown in title block; DocumentNumber: 3; Revision: Use project parameter SCH_Rev; SheetNumber: 4; SheetTotal: 4; PageSetup: Record=PageOptions¦CenterHorizontal=True¦CenterVertical=True¦PrintScale=1.00¦XCorrection=1.00¦YCorrection=1.00¦PrintKind=0¦BorderSize=5000000¦LeftOffset=0¦BottomOffset=0¦Orientation=2¦PaperLength=1000¦PaperWidth=1000¦Scale=100¦PaperSource=15¦PrintQuality=600¦MediaType=1¦DitherType=10¦PaperKind=Letter¦PrintScaleMode=1
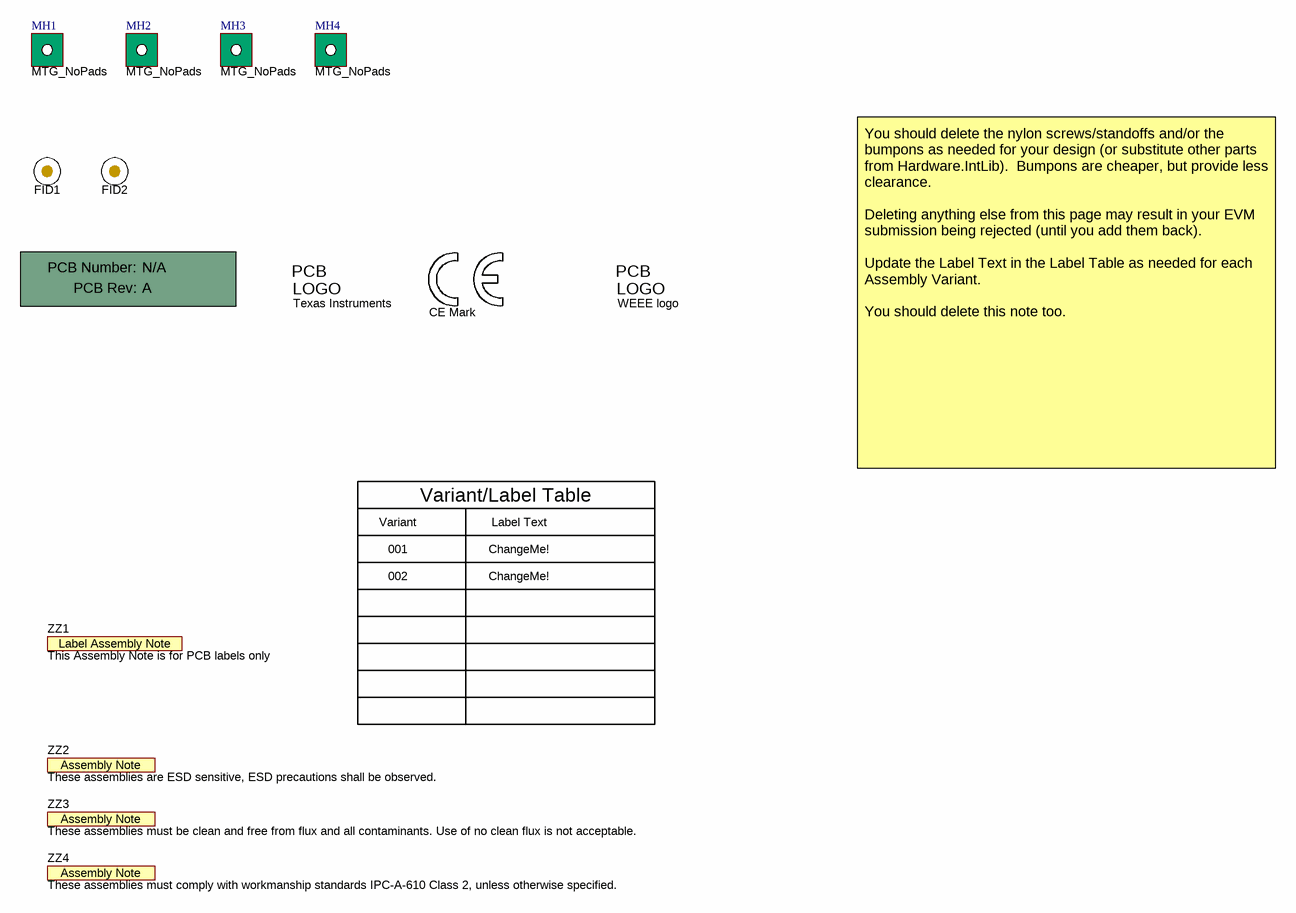
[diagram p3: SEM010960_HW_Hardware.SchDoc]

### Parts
!PCB1  Printed Circuit Board  (value not drawn)  (mechanical)
FID1  Fiducial  [Fiducial10-20]  (value not drawn)
FID2  Fiducial  [Fiducial10-20]  (value not drawn)
Logo1  CE Mark  [CE_Mark_5mm]  (no BOM)
Logo2  Texas Instruments  [TI_Stacked_Overlay_Small]  (no BOM)
Logo4  WEEE logo  [WEEE_Minimum]  (no BOM)
MH1  MTG_NoPads  [NPTH125mil]  (no BOM)
MH2  MTG_NoPads  [NPTH125mil]  (no BOM)
MH3  MTG_NoPads  [NPTH125mil]  (no BOM)
MH4  MTG_NoPads  [NPTH125mil]  (no BOM)
ZZ1  This Assembly Note is for PCB labels only  [AssemblyNoteLabel]  (no BOM)
ZZ2  These assemblies are ESD sensitive, ESD precautions shall be observed.  [AssemblyNote]  (no BOM)
ZZ3  These assemblies must be clean and free from flux and all contaminants. Use of no clean flux is not acceptable.  [AssemblyNote]  (no BOM)
ZZ4  These assemblies must comply with workmanship standards IPC-A-610 Class 2, unless otherwise specified.  [AssemblyNote]  (no BOM)

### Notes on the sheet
- Variant
- Variant/Label Table
- Label Text
- You should delete the nylon screws/standoffs and/or the bumpons as needed for your design (or substitute other parts from Hardware.IntLib).  Bumpons are cheaper, but provide less clearance.
  Deleting anything else from this page may result in your EVM submission being rejected (until you add them back).
  Update the Label Text in the Label Table as needed for each Assembly Variant.
  You should delete this note too.
- 001
- 002
- ChangeMe!

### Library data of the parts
!PCB1 = CMP-0003618-2: Manufacturer: Any
FID1 FID2 = CMP-0077181-1: Fiducial mark.  There is nothing to buy or mount.
Logo1 = CMP-0074844-1: SymbolCreator: a0412235
Logo2 = CMP-0074838-1: Texas Instrument Corporate Signature; SymbolCreator: a0412235; Lib Reference: TI_Logo; Library Reference: Logo
Logo4 = CMP-0074769-1
MH1-MH4 = CMP-0078424-2: PCB Mounting Hole, No Pad; Manufacturer: Any; Key: Mounting Hole (non-standard) No Pad
ZZ1 = CMP-0003616-3
ZZ2 = CMP-0077236-1
ZZ3 = CMP-0077237-1
ZZ4 = CMP-0077238-1

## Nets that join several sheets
DGND: SEM010960_HW_MSPM0 (19 pins), SEM010960_HW_AMC (C13.1 C14.2 DGND.1 FB7.2)
VDD_3V3: SEM010960_HW_MSPM0 (16 pins), SEM010960_HW_AMC (C13.2 FB5.2)
ADC_~{CS}: SEM010960_HW_MSPM0 (J8.2), SEM010960_HW_AMC (U2.19)
ADC_DIN: SEM010960_HW_MSPM0 (J8.6), SEM010960_HW_AMC (U2.20)
ADC_DOUT: SEM010960_HW_MSPM0 (J8.4), SEM010960_HW_AMC (U2.12)
ADC_SCLK: SEM010960_HW_MSPM0 (J8.8), SEM010960_HW_AMC (U2.18)
AMC_~{DRDY}: SEM010960_HW_MSPM0 (J8.12), SEM010960_HW_AMC (U2.16)
AMC_SYNC_RESET: SEM010960_HW_MSPM0 (J8.10), SEM010960_HW_AMC (U2.11)
LMK_CLKOUT: SEM010960_HW_MSPM0 (U1.10 Y1.3), SEM010960_HW_AMC (J11.1)

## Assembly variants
001: not fitted D3 D4 D5 D6 D7 FID1 FID2 FID3 R13 R13 R?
